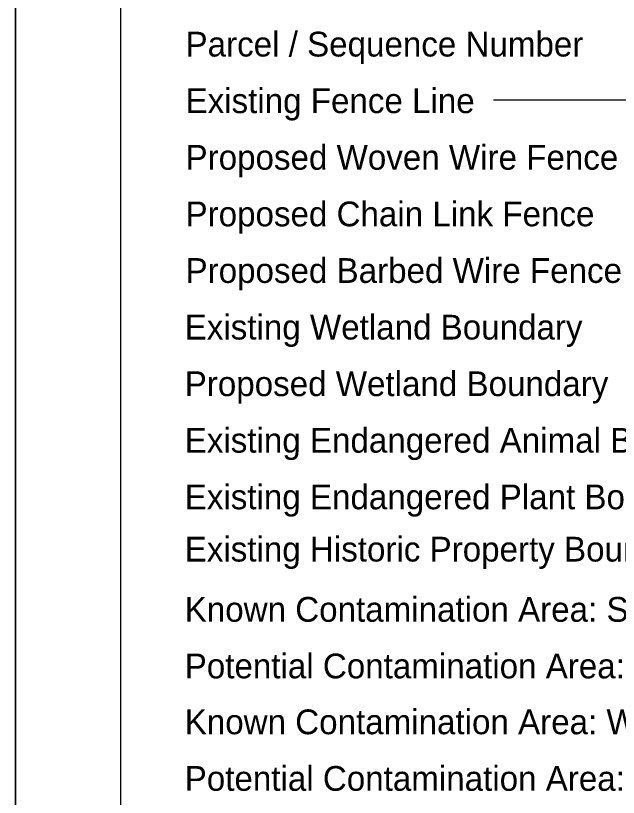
# Model space of a CAD drawing. Extents: x 754056.72 to 754059.56, y 596603.78 to 596605.61.
# Drawn here: x 754056.7248 to 754057.0827, y 596604.6824 to 596605.147 of the extents above; entities that cross this region are included whole.
import ezdxf

# ---------------------------------------------------------------- set-up
doc = ezdxf.new("R2010")
doc.units = 0
for name, color, linetype in [('Sheet_Plan', 7, 'Continuous'), ('Sheet_Plot_Border_Outside_CELL', 7, 'Continuous'), ('Sheet_Symbology', 7, 'Continuous'), ('z - Construction', 7, 'Continuous')]:
    doc.layers.add(name, color=color, linetype=linetype)

msp = doc.modelspace()

# ---------------------------------------------------------------- linework, layer by layer
at = {"layer": 'Sheet_Plan'}
msp.add_line((754056.78734, 596603.84076), (754056.78733, 596605.54909), dxfattribs=at)
at = {"layer": 'Sheet_Plot_Border_Outside_CELL'}
msp.add_lwpolyline([(754056.72484, 596605.61159), (754059.55817, 596605.61159), (754059.55817, 596603.77826), (754056.72484, 596603.77826)], close=True, dxfattribs=at)
at = {"layer": 'Sheet_Symbology'}
msp.add_line((754057.25263, 596605.09667), (754057.00862, 596605.09667), dxfattribs=at)
at = {"layer": 'z - Construction'}
msp.add_line((754056.72484, 596605.61159), (754056.72484, 596603.77826), dxfattribs=at)

# ---------------------------------------------------------------- texts
at = {"layer": 'Sheet_Symbology'}
for s, p in [('Parcel / Sequence Number', (754056.82573, 596605.12267)), ('Existing Fence Line', (754056.82573, 596605.08904)), ('Proposed Woven Wire Fence', (754056.82573, 596605.05541)), ('Proposed Chain Link Fence', (754056.82573, 596605.02178)), ('Proposed Barbed Wire Fence', (754056.82573, 596604.98815)), ('Existing Wetland Boundary', (754056.82524, 596604.95451)), ('Proposed Wetland Boundary', (754056.82524, 596604.92088)), ('Existing Endangered Animal Boundary', (754056.82524, 596604.88727)), ('Existing Endangered Plant Boundary', (754056.82524, 596604.85364)), ('Existing Historic Property Boundary', (754056.82524, 596604.82258)), ('Known Contamination Area: Soil', (754056.82524, 596604.7868)), ('Potential Contamination Area: Soil', (754056.82524, 596604.75317)), ('Known Contamination Area: Water', (754056.82524, 596604.71997)), ('Potential Contamination Area: Water', (754056.82524, 596604.68634))]:
    msp.add_text(s, height=0.0147137, dxfattribs=at).set_placement(p)

doc.saveas('drawing.dxf')
